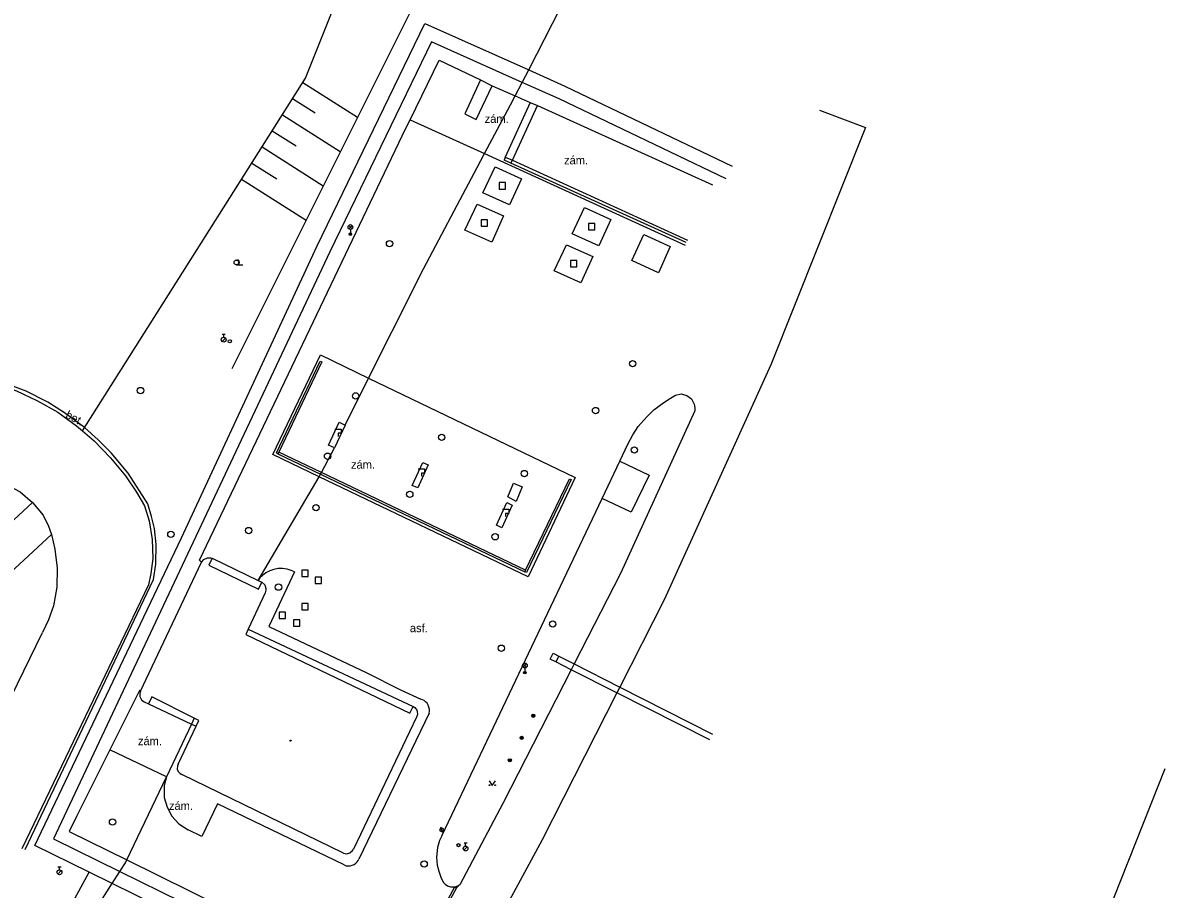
# Model space of a CAD drawing. Extents: x -602419 to -601554, y -1162937 to -1162362.
# Drawn here: x -601739.3 to -601649.5, y -1162616.8 to -1162548.7 of the extents above; entities that cross this region are included whole.
import ezdxf

# ---------------------------------------------------------------- set-up
doc = ezdxf.new("R2010")
doc.units = 0
doc.layers.add('Podklad', color=7, linetype='Continuous')

msp = doc.modelspace()

# ---------------------------------------------------------------- linework, layer by layer
at = {"layer": 'Podklad'}
for p, q in [((-601713.6525, -1162564.89), (-601713.3875, -1162564.625)), ((-601713.6525, -1162564.625), (-601713.3875, -1162564.89)), ((-601713.52, -1162564.945), (-601713.52, -1162565.32)), ((-601722.48, -1162567.7275), (-601721.98, -1162567.7275)), ((-601723.609, -1162573.746), (-601723.344, -1162573.481)), ((-601723.605, -1162573.1725), (-601723.355, -1162573.1725)), ((-601723.48, -1162573.4225), (-601723.48, -1162573.1725)), ((-601699.9325, -1162599.35), (-601699.6675, -1162599.085)), ((-601699.9325, -1162599.085), (-601699.6675, -1162599.35)), ((-601699.8, -1162599.405), (-601699.8, -1162599.78)), ((-601706.406, -1162612.2417), (-601706.294, -1162612.0183)), ((-601704.585, -1162613.1625), (-601704.335, -1162613.1625)), ((-601704.46, -1162613.4125), (-601704.46, -1162613.1625)), ((-601704.589, -1162613.736), (-601704.324, -1162613.471)), ((-601736.515, -1162615.0324), (-601736.265, -1162615.0324)), ((-601736.39, -1162615.2824), (-601736.39, -1162615.0324)), ((-601736.519, -1162615.6059), (-601736.254, -1162615.3409))]:
    msp.add_line(p, q, dxfattribs=at)
for points in [[(-601734.59, -1162580.77), (-601717.04, -1162553.06), (-601708.29, -1162531.19), (-601693.48, -1162491.34), (-601681.9183, -1162447.6661), (-601678.2, -1162433.62)], [(-601712.09, -1162576.63), (-601708.41, -1162569.3), (-601708.01, -1162568.5), (-601705.12, -1162563.04), (-601703.55, -1162560.08), (-601702.97, -1162558.99), (-601700.94, -1162555.15), (-601700.57, -1162554.45), (-601700, -1162553.39), (-601699.49, -1162552.41), (-601697.63, -1162548.77), (-601695.23, -1162544.05)], [(-601712.09, -1162576.63), (-601708.41, -1162569.3), (-601708.01, -1162568.5), (-601705.12, -1162563.04), (-601703.55, -1162560.08), (-601702.97, -1162558.99), (-601700.94, -1162555.15), (-601700.57, -1162554.45), (-601700, -1162553.39), (-601699.49, -1162552.41), (-601697.63, -1162548.77), (-601695.23, -1162544.05)], [(-601708.28, -1162546.74), (-601722.84, -1162575.9)], [(-601738.32, -1162613.36), (-601726.8, -1162589.18), (-601716.12, -1162566.24), (-601707.6599, -1162548.75)], [(-601707.6599, -1162548.75), (-601699.49, -1162552.41), (-601696.65, -1162553.68), (-601683.5, -1162559.9699)], [(-601683.9699, -1162560.96), (-601697.11, -1162554.68), (-601700, -1162553.39), (-601707.14, -1162550.19), (-601715.13, -1162566.71), (-601736.86, -1162612.85)], [(-601708.82, -1162556.32), (-601706.53, -1162551.64), (-601703.29, -1162553.19)], [(-601717.25, -1162553.4), (-601712.96, -1162556.11)], [(-601703.29, -1162553.19), (-601704.53, -1162555.87), (-601703.62, -1162556.3), (-601702.36, -1162553.67)], [(-601703.29, -1162553.19), (-601702.36, -1162553.67)], [(-601702.36, -1162553.67), (-601700.57, -1162554.45), (-601699.39, -1162554.9699)], [(-601718.06, -1162554.6599), (-601716.29, -1162555.78)], [(-601699.39, -1162554.9699), (-601701.34, -1162559.26)], [(-601699.39, -1162554.9699), (-601698.82, -1162555.2)], [(-601700.77, -1162559.5), (-601698.82, -1162555.2)], [(-601698.82, -1162555.2), (-601685.06, -1162561.45)], [(-601676.64, -1162555.58), (-601673.03, -1162556.93), (-601680.46, -1162575.6), (-601688.84, -1162594.07), (-601692.33, -1162600.92)], [(-601725.2199, -1162591.09), (-601725.37, -1162590.95), (-601709.15, -1162556.99), (-601708.82, -1162556.32)], [(-601718.86, -1162555.93), (-601714.31, -1162558.81)], [(-601708.82, -1162556.32), (-601702.97, -1162558.99), (-601687.2, -1162566.19)], [(-601719.6599, -1162557.2), (-601717.79, -1162558.38)], [(-601720.46, -1162558.46), (-601715.65, -1162561.51)], [(-601701.34, -1162559.26), (-601701.44, -1162559.5)], [(-601701.34, -1162559.26), (-601700.77, -1162559.5)], [(-601721.27, -1162559.73), (-601719.29, -1162560.98)], [(-601703.1, -1162562.08), (-601702.14, -1162560.03), (-601700.07, -1162560.96), (-601701, -1162563.02), (-601703.1, -1162562.08)], [(-601700.9099, -1162559.73), (-601701.44, -1162559.5)], [(-601700.9099, -1162559.73), (-601700.77, -1162559.5)], [(-601687.13, -1162565.9699), (-601700.9099, -1162559.73)], [(-601700.77, -1162559.5), (-601687.02, -1162565.8)], [(-601722.07, -1162561), (-601717, -1162564.21)], [(-601704.51, -1162565), (-601703.55, -1162562.95), (-601701.48, -1162563.88), (-601702.4099, -1162565.95), (-601704.51, -1162565)], [(-601696.08, -1162565.28), (-601695.12, -1162563.23), (-601693.05, -1162564.1599), (-601693.98, -1162566.23), (-601696.08, -1162565.28)], [(-601691.4, -1162567.4), (-601690.44, -1162565.35), (-601688.37, -1162566.28), (-601689.3, -1162568.35), (-601691.4, -1162567.4)], [(-601697.49, -1162568.2), (-601696.53, -1162566.15), (-601694.46, -1162567.08), (-601695.39, -1162569.15), (-601697.49, -1162568.2)], [(-601715.98, -1162584.38), (-601719.62, -1162582.63), (-601715.88, -1162574.81)], [(-601719.21, -1162582.58), (-601719.34, -1162582.51), (-601715.89, -1162575.29), (-601715.76, -1162575.35), (-601719.14, -1162582.44)], [(-601715.88, -1162574.81), (-601712.09, -1162576.63)], [(-601741.51, -1162577.02), (-601739.78, -1162577.63), (-601738.13, -1162578.4099), (-601736.53, -1162579.31), (-601735.04, -1162580.38), (-601734.59, -1162580.77), (-601733.65, -1162581.57), (-601732.37, -1162582.89), (-601731.21, -1162584.3), (-601730.33, -1162585.59), (-601729.7, -1162586.6599), (-601729.34, -1162587.84), (-601729.1, -1162589.32), (-601729.05, -1162590.81), (-601729.2, -1162591.99), (-601729.4, -1162592.88)], [(-601734.42, -1162580.5), (-601735.99, -1162579.35), (-601737.31, -1162578.52), (-601739.02, -1162577.65), (-601741.43, -1162576.76)], [(-601712.09, -1162576.63), (-601695.84, -1162584.43), (-601699.55, -1162592.26), (-601715.98, -1162584.38)], [(-601713.93, -1162580.32), (-601712.09, -1162576.63)], [(-601691.7, -1162581.83), (-601691.3, -1162581.08), (-601690.88, -1162580.43), (-601690.24, -1162579.69), (-601689.6599, -1162579.13), (-601688.88, -1162578.54), (-601688.35, -1162578.21), (-601687.9699, -1162577.96), (-601687.52, -1162577.88), (-601687.07, -1162577.99), (-601686.7, -1162578.26), (-601686.49, -1162578.67), (-601686.43, -1162578.96), (-601686.45, -1162579.19)], [(-601686.45, -1162579.19), (-601692.27, -1162591.98), (-601695.92, -1162599.1)], [(-601715.23, -1162581.9), (-601714.4, -1162580.1), (-601713.93, -1162580.32), (-601714.76, -1162582.12), (-601715.23, -1162581.9)], [(-601729.01, -1162592.45), (-601728.81, -1162591.25), (-601728.8, -1162589.71), (-601728.93, -1162588.46), (-601729.15, -1162587.52), (-601729.45, -1162586.52), (-601730.99, -1162584.11), (-601732.32, -1162582.5), (-601733.34, -1162581.4699), (-601734.42, -1162580.5)], [(-601714.74, -1162580.6449), (-601714.24, -1162580.6449), (-601714.24, -1162580.9699), (-601714.49, -1162580.9699), (-601714.49, -1162581.2199)], [(-601692.33, -1162583.1599), (-601691.7, -1162581.83)], [(-601719.14, -1162582.44), (-601719.21, -1162582.58)], [(-601719.21, -1162582.58), (-601715.87, -1162584.18)], [(-601715.8, -1162584.04), (-601719.14, -1162582.44)], [(-601715.8, -1162584.04), (-601714.76, -1162582.12)], [(-601708.65, -1162585.06), (-601707.81, -1162583.26), (-601707.4, -1162583.45), (-601708.2199, -1162585.26), (-601708.65, -1162585.06)], [(-601693.7199, -1162586.09), (-601692.33, -1162583.1599)], [(-601692.33, -1162583.1599), (-601690.04, -1162584.25), (-601691.44, -1162587.17), (-601693.7199, -1162586.09)], [(-601748.8, -1162585.4), (-601747.5, -1162584.86), (-601746.15, -1162584.48), (-601744.74, -1162584.39), (-601743.26, -1162584.42), (-601742.07, -1162584.56), (-601740.71, -1162584.9099), (-601739.48, -1162585.58), (-601738.5, -1162586.42)], [(-601720.78, -1162592.53), (-601715.98, -1162584.38)], [(-601715.98, -1162584.38), (-601715.87, -1162584.18)], [(-601715.87, -1162584.18), (-601715.8, -1162584.04)], [(-601715.87, -1162584.18), (-601699.81, -1162591.86)], [(-601699.75, -1162591.7199), (-601715.8, -1162584.04)], [(-601708.18, -1162583.765), (-601707.68, -1162583.765), (-601707.68, -1162584.09), (-601707.93, -1162584.09), (-601707.93, -1162584.34)], [(-601696.29, -1162584.54), (-601696.1599, -1162584.6), (-601699.68, -1162591.92), (-601699.81, -1162591.86)], [(-601699.75, -1162591.7199), (-601696.29, -1162584.54)], [(-601700.7, -1162584.9), (-601700.01, -1162585.18), (-601700.48, -1162586.32), (-601701.14, -1162585.9699), (-601700.7, -1162584.9)], [(-601706.29, -1162612.54), (-601693.7199, -1162586.09)], [(-601738.5, -1162586.42), (-601743.6599, -1162591.1599)], [(-601738.5, -1162586.42), (-601737.68, -1162587.4099), (-601737.25, -1162588.27), (-601737.02, -1162588.92)], [(-601702.04, -1162588.19), (-601701.2199, -1162586.42), (-601700.8, -1162586.62), (-601701.62, -1162588.39), (-601702.04, -1162588.19)], [(-601701.56, -1162586.935), (-601701.06, -1162586.935), (-601701.06, -1162587.26), (-601701.31, -1162587.26), (-601701.31, -1162587.51)], [(-601741.74, -1162593.26), (-601737.02, -1162588.92)], [(-601737.02, -1162588.92), (-601736.76, -1162590.08), (-601736.58, -1162591.56), (-601736.59, -1162593.06), (-601736.86, -1162594.53), (-601737.25, -1162595.64), (-601737.73, -1162596.63)], [(-601725.2199, -1162591.09), (-601725.04, -1162590.88)], [(-601725.04, -1162590.88), (-601724.76, -1162590.76)], [(-601724.76, -1162590.76), (-601724.5, -1162590.75)], [(-601724.38, -1162590.79), (-601724.64, -1162591.33)], [(-601724.5, -1162590.75), (-601724.38, -1162590.79)], [(-601724.38, -1162590.79), (-601720.78, -1162592.53)], [(-601730.01, -1162601.24), (-601725.2199, -1162591.09)], [(-601724.64, -1162591.33), (-601720.73, -1162593.2199)], [(-601717.9, -1162591.86), (-601718.17, -1162591.74), (-601718.5, -1162591.64), (-601718.85, -1162591.59), (-601719.19, -1162591.6), (-601719.53, -1162591.67), (-601719.86, -1162591.78), (-601720.17, -1162591.94), (-601720.44, -1162592.15), (-601720.63, -1162592.34), (-601720.78, -1162592.53)], [(-601699.81, -1162591.86), (-601699.75, -1162591.7199)], [(-601739.09, -1162613.68), (-601729.01, -1162592.45)], [(-601720.78, -1162592.53), (-601720.4699, -1162592.68)], [(-601720.73, -1162593.2199), (-601720.4699, -1162592.68)], [(-601720.4699, -1162592.68), (-601720.25, -1162592.88)], [(-601717.9, -1162591.86), (-601719.94, -1162596.15)], [(-601729.4, -1162592.88), (-601739.36, -1162613.62)], [(-601720.2199, -1162593.52), (-601721.55, -1162596.36)], [(-601720.25, -1162592.88), (-601720.1599, -1162593.1599)], [(-601720.1599, -1162593.31), (-601720.2199, -1162593.52)], [(-601720.1599, -1162593.1599), (-601720.1599, -1162593.31)], [(-601719.94, -1162596.15), (-601712.28, -1162599.78), (-601709.58, -1162601.13), (-601707.98, -1162601.86)], [(-601811.44, -1162699.63), (-601790.2, -1162676.34), (-601776.01, -1162658.53), (-601771.0161, -1162652.0886), (-601765.466, -1162644.9297), (-601762.9, -1162641.62), (-601760.5218, -1162637.8699), (-601758.93, -1162635.36), (-601755.8662, -1162630.788), (-601750.48, -1162622.75), (-601746.602, -1162614.8054), (-601737.73, -1162596.63)], [(-601721.55, -1162596.36), (-601721.75, -1162596.79)], [(-601721.75, -1162596.79), (-601708.84, -1162602.9699)], [(-601721.55, -1162596.36), (-601708.58, -1162602.43)], [(-601697.8, -1162598.71), (-601697.58, -1162598.26)], [(-601697.36, -1162598.93), (-601697.8, -1162598.71)], [(-601697.58, -1162598.26), (-601697.14, -1162598.48)], [(-601697.14, -1162598.48), (-601697.36, -1162598.93)], [(-601696.15, -1162599.55), (-601697.36, -1162598.93)], [(-601697.14, -1162598.48), (-601695.92, -1162599.1)], [(-601696.15, -1162599.55), (-601701.53, -1162610.06), (-601704.9, -1162616.4099)], [(-601695.92, -1162599.1), (-601696.15, -1162599.55)], [(-601692.56, -1162601.37), (-601696.15, -1162599.55)], [(-601695.92, -1162599.1), (-601692.33, -1162600.92)], [(-601730.11, -1162601.19), (-601732.43, -1162605.85)], [(-601730.01, -1162601.24), (-601730.11, -1162601.19)], [(-601730.01, -1162601.24), (-601730.06, -1162601.38)], [(-601730.06, -1162601.38), (-601730.06, -1162601.6599)], [(-601730.06, -1162601.6599), (-601729.93, -1162601.92)], [(-601692.56, -1162601.37), (-601698.45, -1162612.9099), (-601704.1599, -1162623.49), (-601710.2, -1162633.99)], [(-601692.33, -1162600.92), (-601692.56, -1162601.37)], [(-601685.27, -1162605.07), (-601692.56, -1162601.37)], [(-601692.33, -1162600.92), (-601685.06, -1162604.62)], [(-601729.93, -1162601.92), (-601729.74, -1162602.08)], [(-601729.74, -1162602.08), (-601729.39, -1162602.2199)], [(-601729.13, -1162601.68), (-601729.39, -1162602.2199)], [(-601729.39, -1162602.2199), (-601726.01, -1162603.82)], [(-601725.79, -1162603.35), (-601729.13, -1162601.68)], [(-601708.84, -1162602.9699), (-601708.58, -1162602.43)], [(-601708.58, -1162602.43), (-601708.46, -1162602.51)], [(-601708.46, -1162602.51), (-601708.37, -1162602.62)], [(-601707.33, -1162602.9699), (-601707.3, -1162602.82), (-601707.3, -1162602.67), (-601707.34, -1162602.48), (-601707.4, -1162602.33), (-601707.48, -1162602.19), (-601707.6, -1162602.07), (-601707.73, -1162601.98), (-601707.98, -1162601.86)], [(-601725.79, -1162603.35), (-601726.01, -1162603.82)], [(-601725.43, -1162603.53), (-601725.79, -1162603.35)], [(-601708.32, -1162603.28), (-601713.28, -1162613.64)], [(-601707.33, -1162602.9699), (-601712.85, -1162614.43)], [(-601708.37, -1162602.62), (-601708.3, -1162602.74)], [(-601708.27, -1162603.15), (-601708.32, -1162603.28)], [(-601708.3, -1162602.74), (-601708.26, -1162602.87)], [(-601708.25, -1162603.01), (-601708.27, -1162603.15)], [(-601708.26, -1162602.87), (-601708.25, -1162603.01)], [(-601726.01, -1162603.82), (-601727.9699, -1162607.96)], [(-601727.06, -1162606.9699), (-601725.65, -1162603.99)], [(-601726.01, -1162603.82), (-601725.65, -1162603.99)], [(-601725.65, -1162603.99), (-601725.43, -1162603.53)], [(-601732.43, -1162605.85), (-601735.04, -1162611.09), (-601735.62, -1162612.26)], [(-601727.9699, -1162607.96), (-601732.43, -1162605.85)], [(-601727.06, -1162606.9699), (-601727.12, -1162607.1)], [(-601727.12, -1162607.1), (-601727.13, -1162607.37)], [(-601727.13, -1162607.37), (-601727.05, -1162607.56)], [(-601727.05, -1162607.56), (-601726.9099, -1162607.71)], [(-601726.9099, -1162607.71), (-601726.78, -1162607.78)], [(-601714.07, -1162613.96), (-601726.78, -1162607.78)], [(-601696.52, -1162697.57), (-601692.06, -1162691.87), (-601689.66, -1162687.12), (-601677.75, -1162668.51), (-601672.34, -1162657.11), (-601664.71, -1162642.93), (-601661.79, -1162636.71), (-601657.53, -1162627.66), (-601649.46, -1162607.3)], [(-601731.64, -1162615.41), (-601731.2, -1162614.72), (-601731.09, -1162614.5), (-601727.97, -1162607.96)], [(-601727.9699, -1162607.96), (-601728.1599, -1162608.6599), (-601728.15, -1162609.59), (-601727.93, -1162610.36), (-601727.55, -1162611.06), (-601727.01, -1162611.65), (-601726.26, -1162612.14)], [(-601702.61, -1162608.275), (-601702.36, -1162608.65), (-601702.11, -1162608.275)], [(-601714, -1162614.89), (-601723.96, -1162610.09), (-601725.2, -1162612.6599), (-601726.26, -1162612.14)], [(-601735.62, -1162612.26), (-601731.09, -1162614.5), (-601715.99, -1162621.95)], [(-601736.86, -1162612.85), (-601731.64, -1162615.41)], [(-601706.29, -1162612.54), (-601706.51, -1162612.9699), (-601706.67, -1162613.53), (-601706.75, -1162614.29), (-601706.69, -1162614.9), (-601706.56, -1162615.37)], [(-601732.24, -1162616.35), (-601734.06, -1162615.46), (-601738.32, -1162613.36)], [(-601714.07, -1162613.96), (-601713.81, -1162614.01)], [(-601713.81, -1162614.01), (-601713.55, -1162613.94)], [(-601713.55, -1162613.94), (-601713.35, -1162613.76)], [(-601713.35, -1162613.76), (-601713.28, -1162613.64)], [(-601714, -1162614.89), (-601713.85, -1162614.95), (-601713.69, -1162614.9699), (-601713.52, -1162614.96), (-601713.37, -1162614.92), (-601713.2199, -1162614.86), (-601713.08, -1162614.76), (-601712.99, -1162614.6599), (-601712.9, -1162614.54), (-601712.85, -1162614.43)], [(-601746.75, -1162638.71), (-601734.06, -1162615.46)], [(-601732.24, -1162616.35), (-601731.64, -1162615.41)], [(-601731.64, -1162615.41), (-601715.65, -1162623.27), (-601715.24, -1162627.48), (-601716.64, -1162629.79)], [(-601706.56, -1162615.37), (-601706.37, -1162615.93), (-601706.2, -1162616.26)], [(-601757.4, -1162691.44), (-601770.04, -1162707.55), (-601773.99, -1162712.59), (-601775.01, -1162711.79), (-601771.06, -1162706.75), (-601758.44, -1162690.6599), (-601744.1, -1162670.55), (-601729.44, -1162648.7), (-601716.39, -1162627.23), (-601716.71, -1162624), (-601732.24, -1162616.35)], [(-601746.75, -1162638.71), (-601744.01, -1162634.91), (-601741.98, -1162631.71), (-601738.61, -1162626.39), (-601734.96, -1162620.65), (-601732.34, -1162616.52), (-601732.24, -1162616.35)], [(-601712.24, -1162629.74), (-601712.37, -1162629.67), (-601705.3, -1162616.61), (-601705.17, -1162616.68), (-601712.24, -1162629.74)], [(-601706.2, -1162616.26), (-601706.07, -1162616.4099), (-601705.88, -1162616.53), (-601705.64, -1162616.61), (-601705.4099, -1162616.62), (-601705.19, -1162616.58), (-601705.02, -1162616.5), (-601704.9, -1162616.4099)], [(-601705.17, -1162616.68), (-601704.9, -1162616.4099)]]:
    msp.add_lwpolyline(points, dxfattribs=at)
for points in [[(-601701.83, -1162561.77), (-601701.33, -1162561.77), (-601701.33, -1162561.27), (-601701.83, -1162561.27)], [(-601703.24, -1162564.69), (-601702.74, -1162564.69), (-601702.74, -1162564.19), (-601703.24, -1162564.19)], [(-601694.81, -1162564.9699), (-601694.31, -1162564.9699), (-601694.31, -1162564.4699), (-601694.81, -1162564.4699)], [(-601696.2199, -1162567.89), (-601695.7199, -1162567.89), (-601695.7199, -1162567.39), (-601696.2199, -1162567.39)], [(-601717.33, -1162592.2199), (-601716.83, -1162592.2199), (-601716.83, -1162591.7199), (-601717.33, -1162591.7199)], [(-601716.3, -1162592.77), (-601715.8, -1162592.77), (-601715.8, -1162592.27), (-601716.3, -1162592.27)], [(-601717.33, -1162594.84), (-601716.83, -1162594.84), (-601716.83, -1162594.34), (-601717.33, -1162594.34)], [(-601719.11, -1162595.53), (-601718.61, -1162595.53), (-601718.61, -1162595.03), (-601719.11, -1162595.03)], [(-601717.98, -1162596.12), (-601717.48, -1162596.12), (-601717.48, -1162595.62), (-601717.98, -1162595.62)], [(-601706.2943, -1162612.2978), (-601706.1822, -1162612.0743), (-601706.4057, -1162611.9622), (-601706.5178, -1162612.1857)]]:
    msp.add_lwpolyline(points, close=True, dxfattribs=at)
for centre, radius in [((-601713.52, -1162564.7575), 0.1875), ((-601713.52, -1162565.32), 0.1), ((-601713.52, -1162565.32), 0.0723), ((-601713.52, -1162565.32), 0.0438), ((-601710.44, -1162566.06), 0.25), ((-601722.48, -1162567.5398), 0.1875), ((-601723.48, -1162573.61), 0.1875), ((-601723, -1162573.74), 0.125), ((-601691.33, -1162575.5), 0.25), ((-601730.02, -1162577.61), 0.25), ((-601713.1, -1162578.03), 0.25), ((-601694.24, -1162579.18), 0.25), ((-601706.34, -1162581.29), 0.25), ((-601715.31, -1162582.77), 0.25), ((-601691.19, -1162582.28), 0.25), ((-601699.84, -1162584.13), 0.25), ((-601708.85, -1162585.77), 0.25), ((-601716.2199, -1162586.81), 0.25), ((-601727.63, -1162588.9099), 0.25), ((-601721.51, -1162588.61), 0.25), ((-601702.14, -1162589.1), 0.25), ((-601719.17, -1162593.06), 0.25), ((-601697.61, -1162595.96), 0.25), ((-601701.65, -1162597.86), 0.25), ((-601699.8, -1162599.2175), 0.1875), ((-601699.8, -1162599.78), 0.1), ((-601699.8, -1162599.78), 0.0723), ((-601699.8, -1162599.78), 0.0438), ((-601699.14, -1162603.17), 0.125), ((-601699.14, -1162603.17), 0.1), ((-601699.14, -1162603.17), 0.075), ((-601699.14, -1162603.17), 0.05), ((-601699.14, -1162603.17), 0.025), ((-601718.2199, -1162605.12), 0.045), ((-601718.2199, -1162605.12), 0.0199), ((-601700.05, -1162604.9), 0.125), ((-601700.05, -1162604.9), 0.1), ((-601700.05, -1162604.9), 0.075), ((-601700.05, -1162604.9), 0.05), ((-601700.05, -1162604.9), 0.025), ((-601700.98, -1162606.67), 0.125), ((-601700.98, -1162606.67), 0.1), ((-601700.98, -1162606.67), 0.075), ((-601700.98, -1162606.67), 0.05), ((-601700.98, -1162606.67), 0.025), ((-601702.5851, -1162608.6249), 0.025), ((-601702.1354, -1162608.6249), 0.025), ((-601732.2199, -1162611.52), 0.25), ((-601705.02, -1162613.34), 0.125), ((-601704.46, -1162613.6), 0.1875), ((-601707.7199, -1162614.82), 0.25), ((-601736.39, -1162615.4699), 0.1875)]:
    msp.add_circle(centre, radius, dxfattribs=at)
msp.add_arc((-601722.4175, -1162567.5398), 0.1875, 260.405931, 99.594069, dxfattribs=at)

# ---------------------------------------------------------------- texts
for s, p in [(' zám.', (-601703.2, -1162556.57)), (' zám.', (-601696.96, -1162559.83)), (' zám.', (-601713.71, -1162583.75)), ('asf.', (-601708.84, -1162596.6)), (' zám.', (-601730.46, -1162605.48)), (' zám.', (-601728.02, -1162610.57))]:
    msp.add_text(s, height=0.65, dxfattribs=at).set_placement(p)
msp.add_text('bet.', height=0.65, rotation=332.33, dxfattribs=at).set_placement((-601735.98, -1162579.7199))

doc.saveas('drawing.dxf')
